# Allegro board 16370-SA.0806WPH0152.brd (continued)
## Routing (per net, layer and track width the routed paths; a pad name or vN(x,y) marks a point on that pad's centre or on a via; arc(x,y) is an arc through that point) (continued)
PCIE_SLOT0_TXP7: length 50.6
  TOP w0.178: CN1.B45 68.44,51.68 arc(68.45,51.54) 68.36,51.44 68.2,51.36 arc(68.02,51.09) 67.96,50.78 67.96,49.75 65.3,45.96 62.58,31.31 62.52,31.01 58.7,10.49 58.64,10.19 58.43,9.07 57.99,6.68 57.99,6.27 57.65,5.93 GF1.B45
PCIE_SLOT1_CPRSNT1_N: length 110.1
  TOP w0.178: v1(51.17,59.51) 51.72,58.96 55.79,58.96 56.18,58.85 56.43,58.85 58.06,57.23 58.06,56.38 58.58,55.85 70.58,55.85 71.14,55.29 71.14,51.86 72.15,50.84 72.15,49.45 66.68,41.63 64.86,31.31 64.8,31.01 60.65,7.46 GF1.B48 ; CN2.B31 52.76,74.03 47.24,74.03 46.73,73.53 41.77,73.53 40.95,72.71 CN2.B17 40.09,69.3 40.83,68.55 41.23,67.99 42.59,66.63 42.8,66.48 44.02,64.73 45.54,63.67 46.1,63.28 46.24,63.25 47.26,63.08 49.39,61.58 49.41,61.57 v1(49.44,61.57)
  BOTTOM w0.178: v1(51.17,59.51) 49.44,61.24 v1(49.44,61.57)
PCIE_SLOT1_CPRSNT2_N: length 77.6
  TOP w0.178: GF1.B81 93.65,6.95 95.65,18.31 95.65,19.47 93.08,34.06 93,34.52 89.05,56.93 87.6,58.99 83.6,64.7 79.39,67.65 77.25,68.2 74.06,68.76 CN2.B48
PCIE_SLOT1_CPRSNT3_N: length 75.5
  TOP w0.178: CN2.B81 104.09,57.12 107.23,39.29 107.53,37.64 107.61,37.18 107.65,36.93 107.94,35.29 127.69,7.09 127.7,7.08 127.7,5.9 127.65,5.84 GF1.B115
PCIE_SLOT1_RXN0: length 101
  BOTTOM w0.178: CN2.A17 39.74,75.91 arc(39.63,76) 39.5,75.99 39.34,75.91 arc(39.28,75.82) 39.25,75.7 39.25,72.36 arc(39.28,72.24) 39.34,72.14 40.02,71.47 arc(40.19,71.22) 40.25,70.92 40.25,70.17 40.33,69.69 40.69,69.18 51.54,61.58 72.53,57.88 74.22,56.7 75.04,55.52 75.65,54.66 75.69,54.61 75.71,54.52 75.9,53.42 75.9,53.21 71.06,25.75 71.01,25.45 68.73,12.51 68.36,11.99 68.36,11.77 68.06,11.34 67.88,11.3 67.58,10.87 67.61,10.69 67.3,10.26 67.13,10.23 66.82,9.79 66.85,9.62 66.55,9.18 66.37,9.15 65.28,7.58 65.28,6.28 65.65,5.91 GF1.A53
PCIE_SLOT1_RXN1: length 97.1
  BOTTOM w0.178: GF1.A57 69.65,5.93 69.31,6.27 69.31,6.88 69.54,8.18 69.57,8.33 69.8,9.62 69.84,9.87 72.59,25.45 72.64,25.75 77.42,52.87 76.99,55.29 75.31,57.69 73.15,59.2 52.29,62.88 47.79,66.03 46.7,67.59 46.7,67.59 46.25,70.14 46.25,70.89 arc(46.19,71.24) 45.99,71.53 45.44,72.08 arc(45.29,72.3) 45.24,72.56 45.24,75.55 arc(45.17,75.89) 44.98,76.18 44.82,76.26 44.82,76.26 arc(44.73,76.36) 44.74,76.5 CN2.A22
PCIE_SLOT1_RXN2: length 95
  BOTTOM w0.178: CN2.A26 48.74,76.5 arc(48.73,76.36) 48.82,76.26 48.82,76.26 48.98,76.18 arc(49.17,75.89) 49.24,75.55 49.24,72.56 arc(49.29,72.3) 49.44,72.08 49.99,71.53 arc(50.19,71.24) 50.25,70.89 50.25,70.09 50.36,69.47 50.43,69.31 50.43,69.31 51.89,65.78 54.24,64.14 73.43,60.75 73.53,60.65 76.31,58.7 78.36,55.78 80.15,45.58 73.32,6.81 73.32,6.26 73.65,5.93 GF1.A61
PCIE_SLOT1_RXN3: length 93.1
  BOTTOM w0.178: GF1.A65 77.65,5.93 77.31,6.28 77.31,6.78 77.46,7.62 77.81,9.62 78.04,10.95 78.14,11.5 78.16,11.59 78.16,11.6 82.88,38.36 79.72,56.3 77.35,59.69 76.77,60.26 74.05,62.17 56.59,65.25 56.16,65.55 55.73,65.85 54.63,67.42 54.59,67.75 54.25,70.35 54.25,70.37 54.25,70.89 arc(54.19,71.24) 53.99,71.53 53.44,72.08 arc(53.29,72.3) 53.24,72.56 53.24,75.55 arc(53.17,75.89) 52.98,76.18 52.82,76.26 52.82,76.26 arc(52.73,76.36) 52.74,76.5 CN2.A30
PCIE_SLOT1_RXN4: length 88.9
  BOTTOM w0.178: GF1.A69 81.65,5.93 81.32,6.26 81.32,6.97 85.59,31.15 81.07,56.87 78.03,61.21 74.62,63.59 63.53,65.55 60.55,67.63 60.25,69.32 60.25,70.89 arc(60.19,71.24) 59.99,71.53 59.44,72.08 arc(59.29,72.3) 59.24,72.56 59.24,75.55 arc(59.17,75.89) 58.98,76.18 58.82,76.26 58.82,76.26 arc(58.73,76.36) 58.74,76.5 CN2.A36
PCIE_SLOT1_RXN5: length 86.3
  BOTTOM w0.178: GF1.A73 85.65,5.77 85.33,6.1 85.33,9.18 88.16,25.45 82.53,57.47 79.29,62.1 75.09,65.04 71.36,65.7 70.19,65.9 69.82,65.97 67.23,66.42 65.34,67.75 64.89,68.06 64.57,68.85 64.56,68.85 64.57,68.85 64.5,69.01 64.25,70.4 64.25,70.89 arc(64.19,71.24) 63.99,71.53 63.44,72.08 arc(63.29,72.3) 63.24,72.56 63.24,75.55 arc(63.17,75.89) 62.98,76.18 62.82,76.26 arc(62.73,76.36) 62.74,76.5 CN2.A40
PCIE_SLOT1_RXN6: length 84.1
  BOTTOM w0.178: GF1.A77 89.65,5.93 89.34,6.25 89.34,6.67 91.12,16.78 91.12,17.7 90.46,21.46 90.37,21.92 89.47,27.08 88.92,30.18 85.74,47.34 84.35,56.66 84.31,56.89 84.17,57.71 80.24,63.31 75.89,66.35 70.81,67.25 69.21,68.37 68.37,69.57 68.25,70.23 68.25,70.89 arc(68.19,71.24) 67.99,71.53 67.44,72.08 arc(67.29,72.3) 67.24,72.56 67.24,75.55 arc(67.17,75.89) 66.98,76.18 66.82,76.26 arc(66.73,76.36) 66.74,76.5 CN2.A44
PCIE_SLOT1_RXN7: length 81.9
  BOTTOM w0.178: GF1.A81 93.65,5.93 93.34,6.24 93.34,7.21 93.91,10.46 91.97,21.46 91.89,21.92 85.45,58.46 83.8,60.81 81.38,64.27 76.24,67.87 74.21,68.23 72.46,69.46 72.39,69.62 72.39,69.63 72.33,69.79 72.25,70.2 72.25,70.95 arc(72.19,71.27) 72.02,71.53 71.54,72 71.4,72.15 arc(71.28,72.32) 71.24,72.54 71.24,75.55 arc(71.17,75.89) 70.98,76.18 70.82,76.26 arc(70.73,76.36) 70.74,76.5 CN2.A48
PCIE_SLOT1_RXN8: length 80.8
  BOTTOM w0.178: GF1.A86 98.65,5.93 98.26,6.32 98.26,8.03 98.25,8.06 97.99,9.58 98.09,9.73 97.99,10.25 97.85,10.35 97.76,10.88 97.86,11.02 97.77,11.55 97.62,11.65 97.53,12.18 97.63,12.32 97.54,12.85 97.39,12.95 95.89,21.46 95.81,21.92 90.14,54.06 90.04,54.63 89.9,54.84 82.68,65.15 76.89,69.2 76.53,69.64 76.53,69.65 76.42,69.78 76.24,70.2 76.24,70.99 arc(76.19,71.27) 76.03,71.51 75.47,72.06 arc(75.31,72.3) 75.25,72.59 75.25,75.7 arc(75.28,75.82) 75.34,75.91 75.5,75.99 arc(75.63,76) 75.74,75.91 CN2.A53
PCIE_SLOT1_RXN9: length 79.9
  BOTTOM w0.178: GF1.A90 102.65,5.93 102.27,6.31 102.27,7.01 102.24,7.21 102.1,8.01 102.2,8.16 102.11,8.68 101.96,8.78 101.87,9.31 101.46,11.62 99.73,21.46 99.64,21.92 94.55,50.82 84.92,64.57 84.48,65.2 83.24,66.96 83.27,67.14 82.96,67.59 82.79,67.62 82.47,68.06 82.51,68.24 82.19,68.68 82.02,68.71 81.71,69.16 80.38,70.09 80.23,70.3 80.23,70.8 arc(80.15,71.18) 79.94,71.51 79.46,71.98 arc(79.31,72.21) 79.25,72.49 79.25,75.7 arc(79.28,75.82) 79.34,75.91 79.5,75.99 arc(79.63,76) 79.74,75.91 CN2.A57
PCIE_SLOT1_RXN10: length 79.7
  BOTTOM w0.178: CN2.A61 83.74,75.91 arc(83.63,76) 83.5,75.99 83.34,75.91 arc(83.28,75.82) 83.25,75.7 83.25,72.46 arc(83.3,72.25) 83.42,72.07 83.95,71.53 arc(84.17,71.21) 84.24,70.83 84.24,70.4 84.78,67.37 85.08,66.93 85.26,66.9 85.56,66.47 85.53,66.29 85.84,65.86 86.01,65.83 86.32,65.39 86.29,65.22 86.59,64.78 86.77,64.75 87.07,64.31 87.04,64.14 99.23,46.73 106.29,6.67 106.29,6.26 106.65,5.91 GF1.A94
PCIE_SLOT1_RXN11: length 79.8
  BOTTOM w0.178: GF1.A98 110.65,5.87 110.27,6.25 110.27,7.5 109.94,9.37 109.89,9.67 109.59,11.39 109.59,11.4 109.57,11.49 109.48,12.02 109.36,12.69 109.36,12.69 109.34,12.79 104.13,42.34 89.46,63.3 89.17,64.93 89.27,65.07 89.18,65.61 89.03,65.71 88.94,66.25 89.04,66.4 88.94,66.93 88.8,67.03 88.7,67.57 88.81,67.72 88.71,68.25 88.57,68.35 88.26,70.11 88.26,70.91 arc(88.19,71.24) 88,71.52 87.41,72.11 arc(87.29,72.28) 87.25,72.49 87.25,75.7 arc(87.28,75.82) 87.34,75.91 87.5,75.99 arc(87.63,76) 87.74,75.91 CN2.A65
PCIE_SLOT1_RXN12: length 79.8
  BOTTOM w0.178: GF1.A102 114.65,6.01 114.29,6.37 114.29,7.57 114.18,8.17 113.48,12.16 111.84,21.46 111.76,21.92 108.9,38.1 108.4,38.82 94.11,59.23 93.69,61.58 93.79,61.72 93.7,62.25 93.56,62.35 93.46,62.87 93.57,63.02 93.47,63.54 93.33,63.64 93.24,64.17 93.34,64.31 93.24,64.84 93.1,64.94 92.88,66.2 92.24,69.79 92.24,70.81 arc(92.16,71.23) 91.92,71.59 91.51,72 arc(91.3,72.31) 91.23,72.68 91.23,75.51 arc(91.27,75.73) 91.39,75.93 91.5,75.99 91.5,75.99 arc(91.63,76) 91.74,75.91 CN2.A69
PCIE_SLOT1_RXN13: length 79.8
  BOTTOM w0.178: GF1.A106 118.65,6.07 118.29,6.43 118.29,8.15 115.94,21.46 115.86,21.92 113.8,33.63 98.93,54.87 97.81,61.2 97.91,61.35 97.82,61.89 97.67,61.99 97.58,62.52 97.68,62.67 97.58,63.21 97.44,63.31 97.34,63.84 97.45,63.99 97.35,64.53 97.21,64.63 96.23,70.15 96.23,70.91 arc(96.16,71.26) 95.96,71.56 95.42,72.1 arc(95.29,72.3) 95.24,72.53 95.24,75.67 arc(95.27,75.8) 95.34,75.91 95.5,75.99 arc(95.63,76) 95.74,75.91 CN2.A73
PCIE_SLOT1_RXN14: length 79.8
  BOTTOM w0.178: GF1.A110 122.65,6.06 122.28,6.43 122.28,7.29 120.28,18.61 119.78,21.46 119.7,21.92 118.32,29.72 103.68,50.64 103.11,53.86 103.21,54 103.12,54.54 102.97,54.64 102.88,55.18 102.98,55.32 102.88,55.86 102.74,55.96 102.64,56.5 102.75,56.65 102.65,57.18 102.51,57.28 100.22,70.25 100.22,71 arc(100.16,71.32) 99.98,71.58 99.34,72.22 99.23,72.49 99.23,75.64 arc(99.26,75.79) 99.34,75.91 99.5,75.99 arc(99.63,76) 99.74,75.91 CN2.A77
PCIE_SLOT1_RXN15: length 79.8
  BOTTOM w0.178: CN2.A81 103.74,75.91 arc(103.63,76) 103.5,75.99 103.5,75.99 103.34,75.91 arc(103.25,75.77) 103.22,75.61 103.22,72.43 arc(103.24,72.32) 103.31,72.22 103.93,71.6 arc(104.19,71.2) 104.28,70.73 104.28,69.97 106.95,54.87 107.09,54.77 107.18,54.24 107.08,54.09 107.18,53.55 107.32,53.45 107.42,52.91 107.32,52.77 107.41,52.23 107.56,52.13 107.65,51.59 107.55,51.45 108.44,46.37 123.02,25.55 123.66,21.92 123.74,21.46 125.33,12.45 125.97,8.85 126.09,8.17 126.17,7.68 126.2,7.53 126.22,7.43 126.29,7.02 126.29,6.36 126.65,6 GF1.A114
PCIE_SLOT1_RXP0: length 101
  BOTTOM w0.178: CN2.A16 39.44,76.5 arc(39.45,76.37) 39.36,76.26 39.17,76.16 arc(39.15,76.15) 39.12,76.13 arc(39,75.93) 38.95,75.71 38.95,72.36 arc(39,72.12) 39.13,71.93 39.8,71.25 arc(39.9,71.1) 39.94,70.92 39.94,70.15 40.04,69.57 40.47,68.96 51.42,61.29 72.41,57.59 74,56.48 74.94,55.14 75.41,54.47 75.6,53.39 75.6,53.24 70.75,25.75 70.7,25.45 68.44,12.63 68.11,12.16 68.08,12.12 66.5,9.86 66.12,9.32 64.97,7.68 64.97,6.26 64.65,5.93 GF1.A52
PCIE_SLOT1_RXP1: length 97.1
  BOTTOM w0.178: GF1.A56 68.65,5.89 69.01,6.25 69.01,6.91 69.24,8.23 69.28,8.48 69.49,9.67 69.54,9.92 69.67,10.68 69.57,10.82 69.66,11.35 69.81,11.45 69.9,11.97 69.8,12.12 69.89,12.64 70.04,12.74 70.13,13.27 70.03,13.41 70.12,13.94 70.26,14.04 72.28,25.45 72.33,25.75 77.11,52.87 76.7,55.17 75.49,56.9 75.09,57.47 73.03,58.92 52.17,62.59 47.57,65.81 46.42,67.47 46.4,67.54 45.95,70.11 45.95,70.89 arc(45.9,71.12) 45.77,71.32 45.22,71.87 arc(45.01,72.19) 44.93,72.56 44.93,75.55 arc(44.9,75.75) 44.79,75.93 44.68,75.99 44.68,75.99 arc(44.55,76) 44.44,75.91 CN2.A21
PCIE_SLOT1_RXP2: length 95
  BOTTOM w0.178: CN2.A25 48.44,75.91 arc(48.55,76) 48.68,75.99 48.68,75.99 48.79,75.93 arc(48.9,75.75) 48.93,75.55 48.93,72.56 arc(49.01,72.19) 49.22,71.87 49.77,71.32 arc(49.9,71.12) 49.95,70.89 49.95,70.12 49.95,70.06 50.08,69.35 50.14,69.19 50.15,69.19 51.64,65.59 54.12,63.85 73.26,60.47 73.28,60.47 73.34,60.42 76.1,58.49 76.62,57.73 77.82,56.02 78.07,55.66 79.85,45.58 73.95,12.15 73.81,12.05 73.71,11.52 73.81,11.38 73.72,10.85 73.58,10.75 73.48,10.23 73.59,10.08 73.49,9.56 73.35,9.46 73.26,8.93 73.36,8.79 73.01,6.84 73.01,6.3 72.65,5.93 GF1.A60
PCIE_SLOT1_RXP3: length 93.1
  BOTTOM w0.178: CN2.A29 52.44,75.91 arc(52.55,76) 52.68,75.99 52.68,75.99 52.79,75.93 arc(52.9,75.75) 52.93,75.55 52.93,72.56 arc(53.01,72.19) 53.22,71.87 53.77,71.32 arc(53.9,71.12) 53.95,70.89 53.95,70.33 54.34,67.31 55.52,65.63 56.47,64.96 73.93,61.88 76.58,60.03 77.11,59.49 79.43,56.18 82.57,38.36 79.81,22.73 78.61,15.93 78.47,15.82 78.37,15.3 78.47,15.16 78.38,14.63 78.24,14.53 78.15,14 78.25,13.86 78.15,13.33 78.01,13.23 77.92,12.71 78.02,12.56 77.85,11.62 77.85,11.62 77.84,11.55 77.74,11 77.51,9.67 77.16,7.67 77,6.81 77,6.27 76.65,5.91 GF1.A64
PCIE_SLOT1_RXP4: length 88.9
  BOTTOM w0.178: CN2.A35 58.44,75.91 arc(58.55,76) 58.68,75.99 58.68,75.99 58.79,75.93 arc(58.9,75.75) 58.93,75.55 58.93,72.56 arc(59.01,72.19) 59.22,71.87 59.77,71.32 arc(59.9,71.12) 59.95,70.89 59.95,69.29 60.27,67.46 63.41,65.26 74.5,63.31 77.81,60.99 80.78,56.75 85.28,31.15 82.28,14.18 82.14,14.08 82.05,13.56 82.15,13.41 82.06,12.89 81.91,12.79 81.82,12.26 81.92,12.12 81.83,11.59 81.68,11.49 81.59,10.97 81.69,10.82 81.02,7 81.02,6.27 80.65,5.9 GF1.A68
PCIE_SLOT1_RXP5: length 86.3
  BOTTOM w0.178: CN2.A39 62.44,75.91 arc(62.55,76) 62.68,75.99 62.68,75.99 62.79,75.93 arc(62.9,75.75) 62.93,75.55 62.93,72.56 arc(63.01,72.19) 63.22,71.87 63.77,71.32 arc(63.9,71.12) 63.95,70.89 63.95,70.38 64.21,68.89 64.28,68.73 64.28,68.73 64.64,67.86 64.72,67.81 65.16,67.5 67.11,66.14 69.77,65.67 71.31,65.39 74.97,64.75 79.07,61.88 82.24,57.35 87.85,25.45 85.98,14.69 85.84,14.59 85.74,14.06 85.85,13.92 85.75,13.39 85.61,13.29 85.52,12.77 85.62,12.62 85.53,12.1 85.38,12 85.29,11.47 85.39,11.33 85.02,9.2 85.02,6.11 84.65,5.73 GF1.A72
PCIE_SLOT1_RXP6: length 84.1
  BOTTOM w0.178: CN2.A43 66.44,75.91 arc(66.55,76) 66.68,75.99 66.68,75.99 66.79,75.93 arc(66.9,75.75) 66.93,75.55 66.93,72.56 arc(67.01,72.19) 67.22,71.87 67.77,71.32 arc(67.9,71.12) 67.95,70.89 67.95,70.2 68.08,69.45 68.99,68.15 70.69,66.96 70.76,66.95 73.3,66.5 75.77,66.06 80.03,63.09 83.88,57.59 84.03,56.74 84.03,56.74 84.05,56.61 85.44,47.29 88.62,30.12 89.72,23.91 90.07,21.92 90.15,21.46 90.81,17.67 90.81,16.8 90.32,14.02 89.84,11.27 89.69,11.17 89.6,10.65 89.7,10.5 89.61,9.98 89.47,9.88 89.37,9.35 89.47,9.21 89.38,8.68 89.24,8.58 89.15,8.06 89.25,7.91 89.03,6.69 89.03,6.25 88.65,5.87 GF1.A76
PCIE_SLOT1_RXP7: length 81.9
  BOTTOM w0.178: GF1.A80 92.65,5.93 93.04,6.32 93.04,7.24 93.04,7.27 93.6,10.46 93.45,11.35 93.3,11.45 93.21,11.97 93.31,12.12 93.22,12.64 93.07,12.74 92.98,13.27 93.08,13.41 92.99,13.94 92.85,14.04 92.75,14.56 92.85,14.71 91.66,21.46 91.58,21.92 85.16,58.34 83.55,60.64 81.16,64.05 76.12,67.58 74.09,67.94 73.16,68.59 72.21,69.26 72.11,69.51 72.11,69.51 72.04,69.67 71.95,70.17 71.95,70.95 arc(71.91,71.15) 71.8,71.31 71.18,71.93 arc(71,72.21) 70.93,72.54 70.93,75.55 arc(70.9,75.75) 70.79,75.93 70.68,75.99 70.68,75.99 arc(70.55,76) 70.44,75.91 CN2.A47
PCIE_SLOT1_RXP8: length 80.7
  BOTTOM w0.178: GF1.A85 97.65,5.93 97.95,6.24 97.95,8.01 96.37,16.98 95.58,21.46 95.5,21.92 89.84,54 89.75,54.51 82.46,64.93 76.68,68.97 76.47,69.23 76.29,69.45 76.29,69.45 76.18,69.58 75.94,70.14 75.94,70.99 arc(75.9,71.15) 75.81,71.29 75.26,71.85 arc(75.03,72.19) 74.95,72.59 74.95,75.71 arc(75,75.93) 75.12,76.13 arc(75.15,76.15) 75.17,76.16 75.36,76.26 arc(75.45,76.37) 75.44,76.5 CN2.A52
PCIE_SLOT1_RXP9: length 80
  BOTTOM w0.178: CN2.A56 79.44,76.5 arc(79.45,76.37) 79.36,76.26 79.17,76.16 arc(79.15,76.15) 79.12,76.13 arc(79,75.93) 78.95,75.71 78.95,72.49 arc(79.03,72.1) 79.25,71.77 79.72,71.29 arc(79.87,71.07) 79.93,70.8 79.93,70.18 79.98,70.13 80.16,69.87 81.49,68.94 83.2,66.49 83.2,66.49 84.23,65.03 84.45,64.71 84.67,64.39 94.26,50.7 99.34,21.92 99.42,21.46 101.16,11.57 101.53,9.5 101.94,7.15 101.97,6.98 101.97,6.25 101.65,5.93 GF1.A89
PCIE_SLOT1_RXP10: length 79.7
  BOTTOM w0.178: CN2.A60 83.44,76.5 arc(83.45,76.37) 83.36,76.26 83.17,76.16 arc(83.15,76.15) 83.12,76.13 arc(83,75.93) 82.95,75.71 82.95,72.46 arc(83.02,72.13) 83.2,71.85 83.74,71.32 arc(83.89,71.09) 83.94,70.83 83.94,70.83 83.94,70.38 84.49,67.25 98.94,46.61 105.99,6.64 105.99,6.27 105.65,5.93 GF1.A93
PCIE_SLOT1_RXP11: length 79.8
  BOTTOM w0.178: CN2.A64 87.44,76.5 arc(87.45,76.37) 87.36,76.26 87.17,76.16 arc(87.15,76.15) 87.12,76.13 arc(87,75.93) 86.95,75.71 86.95,72.49 arc(87.01,72.17) 87.19,71.9 87.79,71.3 arc(87.91,71.12) 87.95,70.91 87.95,70.09 89.17,63.18 103.84,42.23 109.05,12.67 109.05,12.66 109.18,11.96 109.27,11.44 109.28,11.37 109.28,11.37 109.59,9.62 109.64,9.31 109.97,7.47 109.97,6.25 109.65,5.93 GF1.A97
PCIE_SLOT1_RXP12: length 79.8
  BOTTOM w0.178: GF1.A101 113.65,6.01 113.98,6.34 113.98,7.54 113.88,8.12 113.18,12.11 111.53,21.46 111.45,21.92 108.62,37.98 108.09,38.73 101.26,48.49 94.84,57.66 93.82,59.11 92.58,66.15 91.94,69.77 91.94,70.81 arc(91.88,71.11) 91.7,71.38 91.29,71.79 arc(91.02,72.19) 90.92,72.68 90.92,75.51 arc(91,75.87) 91.2,76.18 91.36,76.26 91.36,76.26 arc(91.45,76.36) 91.44,76.5 CN2.A68
PCIE_SLOT1_RXP13: length 79.8
  BOTTOM w0.178: CN2.A72 95.44,76.5 arc(95.45,76.37) 95.36,76.26 95.17,76.16 arc(95,75.94) 94.94,75.67 94.94,72.53 arc(95.01,72.18) 95.2,71.89 95.75,71.34 arc(95.88,71.15) 95.93,70.91 95.93,70.12 98.64,54.75 113.51,33.51 115.55,21.92 115.63,21.46 115.75,20.82 117.98,8.12 117.98,6.46 117.65,6.12 GF1.A105
PCIE_SLOT1_RXP14: length 79.8
  BOTTOM w0.178: CN2.A76 99.44,76.5 arc(99.45,76.37) 99.36,76.26 99.17,76.16 arc(98.99,75.93) 98.92,75.64 98.92,72.43 99.08,72.05 99.76,71.37 arc(99.88,71.2) 99.92,71 99.92,70.22 103.39,50.52 118.04,29.6 119.39,21.92 119.47,21.46 120,18.47 120,18.46 121.57,9.57 121.98,7.26 121.98,6.41 121.65,6.08 GF1.A109
PCIE_SLOT1_RXP15: length 79.8
  BOTTOM w0.178: GF1.A113 125.65,6.02 125.99,6.35 125.99,6.99 125.92,7.37 125.9,7.48 125.87,7.63 125.67,8.8 124.91,13.08 123.43,21.46 123.35,21.92 122.73,25.43 108.16,46.25 103.98,69.94 103.98,70.73 arc(103.91,71.08) 103.71,71.38 103.09,72 arc(102.96,72.2) 102.91,72.43 102.91,75.61 arc(102.98,75.92) 103.17,76.16 103.36,76.26 103.36,76.26 arc(103.45,76.37) 103.44,76.5 CN2.A80
PCIE_SLOT1_TXN0: length 100.9
  TOP w0.178: GF1.B51 63.65,5.96 63.33,6.27 63.33,7.04 63.43,7.6 63.68,9 64.31,12.61 67.56,31.01 67.61,31.31 69.42,41.55 72.47,45.91 75.73,50.57 75.93,50.85 76.47,53.91 76.35,54.61 75.61,55.66 73.93,56.83 72.24,58.02 71.4,58.17 70.51,58.01 67.28,58.58 64.6,58.11 58.97,59.1 57.12,60.4 53.41,61.05 49.7,60.4 49.53,60.4 49.52,60.4 49.34,60.43 49.07,60.48 49.06,60.48 48.92,60.58 47.92,61.28 46.83,62.04 46.71,62.06 46.16,62.16 45.58,62.26 45.42,62.42 43.24,63.95 42.01,65.7 41,66.4 40.05,67.77 38.7,68.71 38.46,69.06 38.24,70.26 38.24,71.04 arc(38.17,71.39) 37.98,71.68 37.82,71.76 37.82,71.76 arc(37.73,71.86) 37.74,72 CN2.B15
PCIE_SLOT1_TXN1: length 96.7
  TOP w0.178: CN2.B20 42.74,71.41 arc(42.63,71.5) 42.5,71.49 42.39,71.43 arc(42.32,71.33) 42.27,71.22 arc(42.24,71.12) 42.23,71.02 42.23,71.02 42.23,70.58 42.38,69.74 42.86,69.05 46.2,66.71 46.38,66.74 46.81,66.44 46.85,66.26 47.28,65.96 47.46,65.99 47.89,65.68 47.92,65.51 48.36,65.2 48.53,65.23 48.97,64.93 49,64.75 51.88,62.74 54.69,62.24 54.73,62.23 57.66,61.72 59.52,60.42 64.59,59.53 67.37,60.02 69.97,59.56 70.87,59.71 73.76,59.21 75.89,57.72 76.79,56.43 77.7,55.12 77.79,54.63 77.94,53.79 77.32,50.29 77.08,49.94 75.56,47.77 74.06,45.64 71.54,31.31 71.48,31.01 68.24,12.61 67.28,7.14 67.28,6.37 67.65,5.99 GF1.B55
PCIE_SLOT1_TXN2: length 93.7
  TOP w0.178: CN2.B24 46.74,71.41 arc(46.63,71.5) 46.5,71.49 46.35,71.34 46.23,71.07 46.23,70.35 47.18,68.89 47.18,68.89 47.26,68.81 49.8,66.59 50.52,66.09 50.69,66.12 51.13,65.81 51.16,65.64 51.6,65.33 51.77,65.36 52.21,65.06 52.24,64.88 53.66,63.89 54.18,63.8 54.33,63.9 54.85,63.81 54.95,63.66 56.25,63.43 58.25,63.08 60.13,61.76 64.67,60.96 67.41,61.44 69.98,60.99 70.88,61.15 74.38,60.53 76.97,58.72 79.05,55.77 79.44,53.52 71.6,9.03 71.7,8.89 71.64,8.58 71.41,7.98 71.34,7.57 71.34,6.22 71.65,5.91 GF1.B59
PCIE_SLOT1_TXN3: length 92.2
  TOP w0.178: GF1.B63 75.65,5.97 75.28,6.34 75.28,7.16 77.15,17.76 79.48,31.01 79.54,31.31 82.17,46.23 80.38,56.37 77.74,60.13 75.37,61.8 70.71,62.62 69.79,62.45 67.44,62.87 64.79,62.4 60.66,63.13 60.38,63.33 60.09,63.53 58.83,64.41 57.66,64.62 57.56,64.76 57.03,64.86 56.89,64.76 56.36,64.85 54.75,65.58 54.69,65.75 54.21,65.97 54.04,65.91 53.56,66.13 53.5,66.3 53.01,66.52 52.85,66.46 52.2,66.75 51.31,67.67 50.74,68.26 50.23,69.99 50.23,71.02 50.23,71.02 arc(50.27,71.24) 50.39,71.43 50.5,71.49 arc(50.63,71.5) 50.74,71.41 CN2.B28
PCIE_SLOT1_TXN4: length 88.4
  TOP w0.178: GF1.B67 79.65,5.91 79.28,6.27 79.28,6.94 79.45,7.86 83.53,31.01 83.58,31.31 84.06,34 84.94,38.99 81.76,57.03 81.65,57.13 78.88,61.09 76.01,63.11 70.7,64.04 69.81,63.88 67.43,64.3 64.83,63.84 61.34,64.46 60.19,65.26 60.16,65.43 59.72,65.74 59.55,65.71 59.11,66.02 59.08,66.19 58.65,66.5 58.47,66.46 58.04,66.77 57.2,67.97 57.23,68.14 56.92,68.58 56.75,68.61 56.44,69.05 56.23,70.23 56.23,71.23 56.3,71.37 56.37,71.43 56.5,71.49 56.5,71.49 arc(56.63,71.5) 56.74,71.41 CN2.B34
PCIE_SLOT1_TXN5: length 86.9
  TOP w0.178: GF1.B71 83.65,6.02 83.28,6.39 83.28,6.81 83.39,7.41 83.39,7.41 83.41,7.54 83.44,7.7 83.74,9.44 83.75,9.44 83.77,9.57 86.07,22.61 86.4,24.49 87.67,31.68 83.08,57.68 80.03,62.04 76.6,64.44 70.65,65.49 69.91,65.35 67.56,65.77 66.18,65.53 66.03,65.63 65.51,65.54 65.41,65.39 64.88,65.3 63.16,65.6 63.06,65.75 62.54,65.84 62.39,65.74 61.87,65.83 61.47,66.11 60.78,67.09 60.46,68.9 60.56,69.05 60.47,69.57 60.33,69.67 60.23,70.2 60.23,71.02 60.23,71.02 arc(60.27,71.24) 60.39,71.43 60.5,71.49 60.5,71.49 arc(60.63,71.5) 60.74,71.41 CN2.B38
PCIE_SLOT1_TXN6: length 83.6
  TOP w0.178: CN2.B42 64.74,71.41 arc(64.63,71.5) 64.5,71.49 64.5,71.49 64.39,71.43 arc(64.27,71.24) 64.23,71.02 64.23,71.02 64.23,70.16 64.45,68.91 64.66,68.63 66.37,67.42 66.37,67.42 69.83,66.81 70.64,66.96 72.15,66.69 72.3,66.79 72.82,66.7 72.92,66.56 73.45,66.46 73.59,66.56 74.12,66.47 74.22,66.33 74.74,66.23 74.89,66.34 75.41,66.24 75.51,66.1 77.17,65.81 81.18,63 84.4,58.4 88.61,34.52 88.69,34.06 90.36,24.57 90.27,24.07 89.61,20.3 89.61,20.3 88.81,15.77 88.81,15.77 87.27,7.02 87.27,6.44 87.65,6.06 GF1.B75
PCIE_SLOT1_TXN7: length 81.1
  TOP w0.178: CN2.B46 68.74,71.41 arc(68.63,71.5) 68.5,71.49 68.5,71.49 68.39,71.43 arc(68.27,71.24) 68.23,71.02 68.23,71.02 68.23,70.2 68.6,69.34 69.12,68.9 69.24,68.84 69.77,68.74 69.91,68.84 70.44,68.75 70.54,68.6 71.06,68.51 71.21,68.61 71.73,68.51 71.83,68.36 72.36,68.27 72.5,68.37 73.03,68.27 73.13,68.13 77.51,67.33 82.37,63.92 85.81,59.01 90.13,34.52 90.21,34.06 93.05,17.98 92.45,14.58 91.67,10.15 91.29,8.03 91.29,6.38 91.65,6.02 GF1.B79
PCIE_SLOT1_TXN8: length 79.5
  TOP w0.178: GF1.B84 96.65,5.98 96.33,6.29 96.33,8.58 97.74,16.56 94.65,34.06 94.57,34.52 90.51,57.54 84.98,65.45 84.83,65.59 84.83,65.6 84.71,65.72 80.58,68.61 77.37,69.17 76.55,69.85 76.24,70.3 76.24,71.01 arc(75.98,71.64) 75.35,71.9 74.91,71.9 arc(74.71,71.86) 74.54,71.75 74.47,71.68 arc(74.24,71.58) 74,71.66 arc(73.99,71.67) 73.98,71.68 73.82,71.76 arc(73.73,71.86) 73.74,72 CN2.B51
PCIE_SLOT1_TXN9: length 77.7
  TOP w0.178: CN2.B55 77.74,72 arc(77.73,71.86) 77.82,71.76 77.98,71.68 arc(77.99,71.67) 78,71.66 arc(78.21,71.59) 78.41,71.68 arc(78.6,71.81) 78.82,71.85 79.39,71.85 arc(79.98,71.6) 80.23,71.01 80.23,70.53 80.34,69.91 80.48,69.72 81.77,68.81 83.12,68.57 85.89,66.64 92.66,56.96 96.62,34.52 96.7,34.06 99.59,17.63 100.48,12.57 100.94,10 100.32,6.52 100.32,6.09 100.65,5.76 GF1.B88
PCIE_SLOT1_TXN10: length 76.1
  TOP w0.178: GF1.B92 104.65,5.88 104.33,6.2 104.33,8.78 102.06,12.02 93.83,58.68 88.19,66.74 84.74,69.15 83.07,69.45 82.53,69.83 82.32,70.12 82.24,70.58 82.24,71.05 81.98,71.68 81.82,71.76 arc(81.73,71.86) 81.74,72 CN2.B59
PCIE_SLOT1_TXN11: length 75.1
  TOP w0.178: GF1.B96 108.65,5.97 108.32,6.3 108.32,7.65 106.46,10.3 102.95,15.32 99.65,34.06 99.56,34.52 95.16,59.51 89.15,68.08 86.53,69.92 86.3,70.25 86.22,70.66 86.22,71.22 arc(86.17,71.46) 86.01,71.66 85.82,71.76 arc(85.73,71.87) 85.74,72 CN2.B63
PCIE_SLOT1_TXN12: length 74.7
  TOP w0.178: CN2.B67 89.74,72 arc(89.73,71.86) 89.82,71.76 89.98,71.68 arc(90.18,71.38) 90.25,71.02 90.25,70.11 90.31,69.78 96.32,61.21 101.02,34.52 101.1,34.06 103.62,19.78 106.29,15.96 109.65,11.16 110.82,9.5 111.54,8.47 112.32,7.36 112.32,6.32 112.65,5.99 GF1.B100
PCIE_SLOT1_TXN13: length 74.7
  TOP w0.178: CN2.B71 93.74,72 arc(93.73,71.86) 93.82,71.76 93.98,71.68 arc(94,71.66) 94.02,71.63 arc(94.19,71.35) 94.25,71.02 94.25,70.03 95.22,68.66 96.02,67.51 96.51,66.81 96.86,66.31 96.86,66.3 102.46,34.52 102.54,34.06 103.46,28.86 104.28,24.19 111.54,13.82 111.56,13.8 111.99,13.18 115.38,8.35 116.32,6.99 116.32,6.37 116.65,6.04 GF1.B104
PCIE_SLOT1_TXN14: length 74.9
  TOP w0.178: GF1.B108 120.65,6.06 120.31,6.39 120.31,7.38 119.96,7.89 119.11,9.09 119.11,9.1 118.66,9.74 116.94,12.19 104.81,29.52 98.25,66.7 98.25,70.13 98.25,70.15 arc(98.25,70.16) 98.25,70.16 98.25,71.02 arc(98.18,71.38) 97.98,71.68 97.82,71.76 arc(97.73,71.86) 97.74,72 CN2.B75
PCIE_SLOT1_TXN15: length 75.9
  TOP w0.178: CN2.B79 101.74,72 arc(101.73,71.87) 101.82,71.76 102.01,71.66 arc(102.19,71.43) 102.25,71.15 102.25,70.57 101.16,64.37 100.7,61.75 105.69,33.44 124.31,6.85 124.31,6.23 124.65,5.89 GF1.B112
PCIE_SLOT1_TXP0: length 100.9
  TOP w0.178: CN2.B14 37.44,71.41 arc(37.55,71.5) 37.68,71.49 37.68,71.49 37.79,71.43 arc(37.9,71.25) 37.94,71.04 37.94,71.04 37.94,70.23 38.17,68.94 38.48,68.49 39.83,67.55 40.78,66.19 41.8,65.48 43.02,63.73 45.22,62.19 45.43,61.98 46.66,61.76 46.66,61.76 46.71,61.75 47.75,61.03 48.75,60.33 48.96,60.18 49.02,60.18 49.03,60.18 49.04,60.18 49.29,60.13 49.47,60.1 49.51,60.09 49.73,60.09 53.41,60.74 57,60.11 58.85,58.81 64.6,57.8 67.28,58.27 70.51,57.7 71.4,57.86 72.12,57.73 75.39,55.44 76.06,54.49 76.16,53.91 75.64,50.97 75.48,50.74 69.13,41.67 67.3,31.31 67.25,31.01 64.01,12.66 63.92,12.14 63.78,12.03 63.68,11.51 63.79,11.37 63.69,10.84 63.55,10.74 63.46,10.21 63.56,10.07 63.46,9.54 63.32,9.44 63.23,8.92 63.33,8.77 63.13,7.65 63.03,7.06 63.03,6.31 62.65,5.93 GF1.B50
PCIE_SLOT1_TXP1: length 96.7
  TOP w0.178: GF1.B54 66.65,6.05 66.97,6.37 66.97,7.17 67.94,12.67 71.17,31.01 71.23,31.31 73.77,45.76 77.03,50.41 77.63,53.79 77.49,54.57 77.41,55 75.67,57.5 73.64,58.92 70.87,59.41 69.97,59.25 67.37,59.71 64.59,59.22 59.4,60.13 57.54,61.43 54.68,61.93 54.63,61.94 53.18,62.2 51.76,62.45 42.64,68.83 42.09,69.62 41.93,70.53 41.93,70.53 41.93,71.27 41.98,71.32 arc(42.07,71.51) 42.2,71.68 42.36,71.76 arc(42.45,71.86) 42.44,72 CN2.B19
PCIE_SLOT1_TXP2: length 93.7
  TOP w0.178: CN2.B23 46.44,72 arc(46.46,71.89) 46.41,71.79 46.37,71.79 46.09,71.51 45.94,71.15 45.93,71.14 45.93,70.26 46.96,68.67 47.05,68.59 49.61,66.35 53.54,63.6 56.45,63.09 58.13,62.79 60.02,61.47 64.67,60.65 67.41,61.14 69.98,60.68 70.88,60.84 74.26,60.25 76.75,58.5 78.76,55.65 79.13,53.52 73.25,20.17 71.04,7.6 71.04,6.22 70.65,5.83 GF1.B58
PCIE_SLOT1_TXP3: length 92.2
  TOP w0.178: GF1.B62 74.65,6.02 74.97,6.34 74.97,7.18 76.57,16.23 79.17,31.01 79.23,31.31 81.86,46.23 80.09,56.25 77.52,59.92 75.25,61.51 70.71,62.31 69.79,62.14 67.44,62.56 64.79,62.09 60.54,62.84 60.21,63.08 58.71,64.12 56.27,64.55 52.03,66.5 51.09,67.46 50.81,67.76 50.47,68.11 49.93,69.95 49.93,71.02 arc(50,71.38) 50.2,71.68 50.36,71.76 arc(50.45,71.86) 50.44,72 CN2.B27
PCIE_SLOT1_TXP4: length 88.4
  TOP w0.178: GF1.B66 78.65,5.93 78.98,6.26 78.98,6.96 81.42,20.8 83.22,31.01 83.27,31.31 83.76,34.06 84.63,38.99 81.47,56.89 81.42,56.94 78.66,60.88 75.89,62.82 70.7,63.73 69.81,63.57 67.43,63.99 64.83,63.54 61.22,64.17 57.82,66.55 56.15,68.93 55.93,70.2 55.93,71.3 56.09,71.62 56.36,71.76 56.36,71.76 arc(56.45,71.86) 56.44,72 CN2.B33
PCIE_SLOT1_TXP5: length 87
  TOP w0.178: CN2.B37 60.44,72 arc(60.45,71.86) 60.36,71.76 60.2,71.68 arc(60,71.38) 59.93,71.02 59.93,70.17 60.49,66.98 61.25,65.89 61.75,65.54 64.88,64.99 67.56,65.46 69.91,65.05 70.65,65.18 76.48,64.15 79.81,61.82 82.79,57.56 87.36,31.68 86.12,24.64 86.12,24.64 85.77,22.66 83.47,9.62 83.44,9.5 83.14,7.75 83.11,7.59 83.08,7.44 82.98,6.83 82.98,6.35 82.65,6.02 GF1.B70
PCIE_SLOT1_TXP6: length 83.6
  TOP w0.178: GF1.B74 86.65,6.08 86.96,6.39 86.96,7.04 88.51,15.82 88.53,15.95 88.53,15.95 89.28,20.2 89.97,24.12 90.05,24.57 88.38,34.06 88.3,34.52 84.11,58.28 80.96,62.78 77.05,65.52 70.64,66.65 69.83,66.5 66.25,67.13 64.44,68.41 64.16,68.79 63.93,70.14 63.93,71.02 arc(64,71.38) 64.2,71.68 64.36,71.76 arc(64.45,71.86) 64.44,72 CN2.B41
PCIE_SLOT1_TXP7: length 81.1
  TOP w0.178: GF1.B78 90.65,6.04 90.99,6.38 90.99,8.05 91.37,10.2 91.84,12.87 92.15,14.64 92.74,17.98 89.9,34.06 89.82,34.52 85.52,58.89 82.16,63.7 77.39,67.04 69.13,68.55 69.13,68.55 68.97,68.63 68.35,69.15 67.93,70.14 67.93,71.02 arc(68,71.38) 68.2,71.68 68.36,71.76 arc(68.45,71.86) 68.44,72 CN2.B45
PCIE_SLOT1_TXP8: length 79.5
  TOP w0.178: GF1.B83 95.65,5.91 96.03,6.29 96.03,8.63 96.03,8.63 96.23,9.76 96.13,9.9 96.22,10.43 96.37,10.53 96.46,11.05 96.36,11.2 96.45,11.72 96.6,11.82 96.69,12.35 96.59,12.49 96.68,13.02 96.82,13.12 97.43,16.56 94.34,34.06 94.26,34.52 90.23,57.42 84.74,65.25 84.62,65.38 84.61,65.38 84.49,65.5 80.46,68.32 77.24,68.89 76.32,69.64 75.94,70.21 75.94,71.01 arc(75.77,71.43) 75.35,71.6 74.91,71.6 arc(74.83,71.58) 74.76,71.53 74.69,71.47 arc(74.25,71.27) 73.8,71.43 73.68,71.49 73.68,71.49 arc(73.55,71.5) 73.44,71.41 CN2.B50
PCIE_SLOT1_TXP9: length 77.7
  TOP w0.178: CN2.B54 77.44,71.41 arc(77.55,71.5) 77.68,71.49 77.68,71.49 77.8,71.43 arc(78.22,71.29) 78.63,71.47 arc(78.71,71.52) 78.82,71.55 79.39,71.55 arc(79.77,71.39) 79.93,71.01 79.93,70.5 80.05,69.79 80.26,69.5 81.65,68.52 83,68.28 85.67,66.42 92.37,56.84 96.31,34.52 96.39,34.06 99.45,16.65 99.55,16.12 99.45,15.98 99.54,15.46 99.68,15.35 99.78,14.83 99.67,14.69 99.77,14.16 99.91,14.06 100,13.53 99.9,13.39 100,12.86 100.14,12.76 100.18,12.51 100.4,11.28 100.63,10 100.02,6.55 100.02,6.12 99.65,5.76 GF1.B87
PCIE_SLOT1_TXP10: length 76.1
  TOP w0.178: CN2.B58 81.44,71.41 arc(81.55,71.5) 81.68,71.49 81.74,71.46 81.93,70.99 81.93,70.53 81.94,70.53 82.03,70 82.31,69.61 82.95,69.16 84.62,68.86 87.97,66.52 89.39,64.49 89.36,64.31 89.67,63.87 89.85,63.84 90.16,63.39 90.13,63.22 90.44,62.77 90.62,62.74 90.93,62.29 90.9,62.12 91.21,61.67 91.39,61.64 93.54,58.56 101.77,11.9 104.02,8.68 104.02,6.21 103.65,5.84 GF1.B91
PCIE_SLOT1_TXP11: length 75.1
  TOP w0.178: CN2.B62 85.44,71.41 arc(85.55,71.5) 85.68,71.49 85.84,71.41 arc(85.9,71.32) 85.92,71.22 85.92,70.63 86.01,70.13 86.31,69.7 88.94,67.86 89.72,66.75 89.69,66.58 89.99,66.14 90.16,66.11 90.47,65.67 90.44,65.5 90.75,65.06 90.92,65.03 91.23,64.59 91.19,64.42 91.5,63.98 91.67,63.95 94.87,59.39 99.25,34.52 99.34,34.06 102.66,15.2 103.5,14.01 106.21,10.13 108.01,7.56 108.01,6.34 107.65,5.98 GF1.B95
PCIE_SLOT1_TXP12: length 74.6
  TOP w0.178: CN2.B66 89.44,71.41 arc(89.55,71.5) 89.68,71.49 89.68,71.49 89.79,71.43 arc(89.91,71.24) 89.95,71.02 89.95,71.02 89.95,70.09 90.02,69.66 91.7,67.27 91.67,67.09 91.98,66.66 92.15,66.63 92.45,66.19 92.42,66.02 92.73,65.58 92.9,65.55 93.21,65.11 93.18,64.94 93.48,64.5 93.66,64.47 96.03,61.09 100.71,34.52 100.79,34.06 103.33,19.66 106.04,15.79 109.4,10.99 110.48,9.44 112.01,7.26 112.01,6.3 111.65,5.94 GF1.B99
PCIE_SLOT1_TXP13: length 74.6
  TOP w0.178: GF1.B103 115.65,6 116.02,6.37 116.02,6.9 114.23,9.44 111.69,13.08 111.31,13.63 111.31,13.63 103.99,24.07 103.16,28.81 102.23,34.06 102.15,34.52 97.25,62.31 97.11,62.41 97.01,62.94 97.11,63.08 97.02,63.61 96.88,63.71 96.79,64.23 96.89,64.38 96.79,64.9 96.65,65 96.56,65.53 96.66,65.67 96.57,66.2 96.26,66.64 95.77,67.33 94.97,68.48 93.95,69.94 93.95,71.02 93.95,71.02 arc(93.91,71.24) 93.79,71.43 93.74,71.46 93.68,71.49 arc(93.55,71.5) 93.44,71.41 CN2.B70
PCIE_SLOT1_TXP14: length 74.8
  TOP w0.178: GF1.B107 119.65,6.01 120.01,6.37 120.01,7.28 119.71,7.71 118.69,9.17 118.51,9.2 118.2,9.65 118.23,9.82 117.92,10.27 117.74,10.3 117.43,10.75 117.46,10.92 117.15,11.37 116.98,11.4 116.66,11.85 116.69,12.02 104.52,29.4 97.95,66.68 97.95,70.11 arc(97.95,70.14) 97.95,70.16 97.95,71.02 97.95,71.02 arc(97.91,71.24) 97.79,71.43 97.68,71.49 97.68,71.49 arc(97.55,71.5) 97.44,71.41 CN2.B74
PCIE_SLOT1_TXP15: length 75.8
  TOP w0.178: CN2.B78 101.44,71.41 arc(101.55,71.5) 101.68,71.49 101.84,71.41 arc(101.92,71.29) 101.95,71.15 101.95,70.6 101.43,67.66 101.29,67.56 101.19,67.04 101.29,66.89 101.2,66.37 101.06,66.27 100.97,65.74 101.07,65.6 100.97,65.07 100.83,64.97 100.74,64.45 100.84,64.3 100.39,61.75 105.4,33.32 124.01,6.75 124.01,6.23 123.65,5.87 GF1.B111
PCIE_SMCLK: length 52.8
  TOP w0.178: U10.1 33.82,41.29 33.55,41.01 33.55,40.2 34.18,39.57 34.93,39.57 v1(35.12,39.76) ; v1(17.19,24.91) 16.5,24.22 16.5,7.99 16.27,7.77 16.27,6.38 15.65,5.75 GF1.B5
  BOTTOM w0.178: v1(17.19,24.91) 17.19,24.91 18.46,24.91 20.62,27.07 27.2,27.07 34.19,34.06 v2(34.19,38) 34.19,38.92 35.02,39.76 v1(35.12,39.76)
PCIE_SMCLK0: length 4.6
  TOP w0.178: RE1.2 32.27,46.13 R14.2 32.48,44.85 32.48,43.61 32.11,43.24 U10.5
PCIE_SMCLK1: length 5.2
  TOP w0.178: v2(27.18,39.09) 27.19,39.09 27.54,39.44 RE10.2 27.98,40.38 28.09,40.5 28.09,40.94 28.33,41.18 R16.2 28.88,41.29 U10.8
PCIE_SMDAT: length 52.7
  TOP w0.178: v1(35.06,38.84) 34.77,39.14 34,39.14 33.11,40.02 33.11,41.19 33.86,41.94 U10.2 ; GF1.B6 16.65,6.14 16.7,6.2 16.7,7.59 16.93,7.82 16.93,23.46 v1(17.25,23.77)
  BOTTOM w0.178: v1(35.06,38.84) 35.22,38.68 35.22,36.43 v2(35.24,36.41) 35.22,36.4 35.22,35.87 34.74,35.38 34.74,34 25.22,24.48 17.95,24.48 v1(17.25,23.77)
PCIE_SMDAT0: length 4.7
  TOP w0.178: U10.4 33.24,43.24 32.91,43.56 32.91,44.68 R13.2 33.28,46.13 RE7.2
PCIE_SMDAT1: length 3.8
  TOP w0.178: U10.7 29.67,41.94 29.28,42.33 R15.2 28.39,42.33 28.17,42.11 28.17,41.79 27.91,41.53 RE9.2
PCIE_WAKE_N: length 82.5
  TOP w0.178: v1(32.99,56.2) 32.1,56.2 31.13,55.24 31.13,53.34 CN1.B11 ; v1(31.45,36.73) 31.84,36.33 31.84,16.76 24.37,9.29 22.39,9.29 21.31,8.21 21.31,6.08 21.65,5.74 GF1.B11
  BOTTOM w0.178: v1(31.45,36.73) 31.45,37.02 31.18,37.28 31.18,39.87 31.84,40.53 31.84,40.53 33.08,41.76 v2(33.08,45.28) 33.08,46.18 34.4,47.5 34.4,48.62 33.96,49.05 33.96,51.32 33.33,51.95 32.52,51.95 CN1.B11 ; v1(32.99,56.2) 34.51,57.73 35.36,57.73 35.78,58.15 35.78,68.32 33.05,71.05 33.05,71.74 CN2.B11
PERST_N: length 32.3
  TOP w0.178: v1(37.76,62.68) 37.45,62.99 R19.1 36.81,62.36 36.64,62.18 U9.4
  BOTTOM w0.178: CN1.A11 32.51,54.89 33.55,55.92 35.27,55.92 35.91,56.56 35.91,57.52 37.33,58.95 37.81,58.95 38.3,59.44 38.3,62.14 v1(37.76,62.68) 37.92,62.84 v2(37.92,66.04) 37.92,68.39 36.24,70.07 36.24,71.39 35.17,72.46 35.17,73.12 35.53,73.48 35.53,74.54 34.38,75.69 32.57,75.69 CN2.A11
PERST_N_1: length 6.1
  TOP w0.178: R6.1 38.85,62.36 v2(38.85,63.06) 38.36,63.56 38.02,63.56 37.8,63.79 37.8,65.13 36.57,66.36 U8.4
PERST_N_1_R: length 6.6
  TOP w0.178: v2(39.58,61.21) 39.58,61.23 39.25,60.9 R6.2 38.31,60.86 38.31,59.19 37.71,58.59 36.29,58.59 35.99,58.9 U9.2
PERST_O_1_R: length 5.5
  TOP w0.178: U8.1 35.08,63.87 34.8,63.58 v2(33.66,63.58) 33.66,62.87 33.83,62.7 R17.2 32.96,62.29 32.89,62.36 R3.2
PERST_O_2_R: length 4.3
  TOP w0.178: U9.1 34.96,59.24 R20.2 R4.2
RESET_IN: length 4.5
  TOP w0.178: R1.2 24.32,66.63 C19.1 R2.1 27.06,66.63 27.59,67.16 U1.3
RESET_O_1: length 3.6
  TOP w0.178: U1.2 29.64,63.87 29.84,63.66 30.56,63.66 v2(30.68,63.53) 31.23,62.99 R3.1
RESET_O_2: length 1.8
  TOP w0.178: R4.1 30.79,60.13 30.24,59.59 U2.2
RESET_P3V3_IN: length 5.4
  TOP w0.178: v2(28.53,63.4) 28.62,63.31 U2.3 26.92,61.82 26.38,61.28 C23.1 26.21,62.29 R5.1
RSVD0: length 7.9
  TOP w0.178: GF1.B30 42.65,11.42 TP6.1
RSVD1: length 8.7
  BOTTOM w0.178: GF1.A19 31.65,6.2 32.45,7 TP7.1
S0_PCIE_SMCLK: length 11.5
  TOP w0.178: RE1.1 32.28,47.42 v1(32.81,47.95)
  BOTTOM w0.178: v1(32.81,47.95) 32.39,48.37 26.98,48.37 26.13,49.22 26.13,52.35 CN1.B5
S0_PCIE_SMDAT: length 9.5
  TOP w0.178: v1(33.72,47.92) 33.72,47.45 RE7.1
  BOTTOM w0.178: v1(33.72,47.92) 33.72,48.1 33.03,48.8 27.58,48.8 27.09,49.29 CN1.B6
S0_SMB_ALERT_B12_N: length 3.1
  TOP w0.178: RE4.1 35.29,48.19 35.09,48.39 CN1.B12
S0_SMB_CLK_A32: length 13.3
  TOP w0.178: CN1.A32 55.09,56.96 54.32,57.73 48.61,57.73 46.07,60.27 44.5,60.27 43.94,60.83 RE2.2
S0_SMB_DAT_A33: length 16.9
  TOP w0.178: RE3.2 43.55,61.97 44.83,60.7 46.25,60.7 48.79,58.16 55.16,58.16 56.09,57.23 CN1.A33
S1_PCIE_SMCLK: length 42.4
  TOP w0.178: RE10.1 25.7,40.38 v1(25.67,40.35)
  BOTTOM w0.178: v1(25.67,40.35) 25,41.03 25,41.65 25.11,41.76 25.11,48.43 24.17,49.37 22.57,49.37 22.09,49.85 22.09,50.82 23.05,51.78 23.05,55.14 22.54,55.66 21.81,56.39 21.81,57.93 19.24,60.5 19.24,68.73 22.19,71.67 25.06,71.67 CN2.B5
S1_PCIE_SMDAT: length 40.7
  TOP w0.178: RE9.1 25.83,41.53 v1(25.67,41.37)
  BOTTOM w0.178: v1(25.67,41.37) 25.54,41.5 25.54,48.61 24.17,49.98 24.17,50.72 25.14,51.68 25.14,55.26 24.5,55.9 22.91,55.9 22.24,56.57 22.24,58.11 19.68,60.68 19.68,68.55 20.9,69.77 26.15,69.77 CN2.B6
S1_SMB_ALERT_B12_N: length 6.9
  TOP w0.178: CN2.B12 35.09,69.02 36.98,67.13 36.98,67 37.88,66.1 37.88,66.1 38.53,65.45 RE8.1
S1_SMB_CLK_A32: length 34.7
  TOP w0.178: RE5.2 40.44,63.95 40.44,64.35 37.46,67.32 37.46,67.33 36.95,67.84 36.95,67.84 35.6,69.18 v1(35.6,69.41) ; v1(34.66,71.95) 35.04,72.33 35.04,72.97 36.34,74.26 42.59,74.26 43.12,74.8 43.12,75.69 43.82,76.39 54.27,76.39 CN2.A32
  BOTTOM w0.178: v1(34.66,71.95) 35.12,71.95 35.93,71.14 35.93,69.74 v1(35.6,69.41)
S1_SMB_DAT_A33: length 33.2
  TOP w0.178: CN2.A33 55.26,76.03 45.42,76.03 44.98,75.58 44.98,74.39 44.42,73.83 37.69,73.83 37.1,73.25 37.1,72.05 36.25,71.19 36.25,69.17 41,64.42 41,64.12 RE6.2
SLOT0_CONFIG: length 38.5
  TOP w0.178: v1(70.5,39.34) 71.07,39.9 R33.1
  BOTTOM w0.178: GF1.A50 62.65,6.32 63.84,7.5 63.84,9.43 65.7,12.09 68.05,25.45 68.11,25.75 68.83,29.85 69.72,34.89 v2(69.99,36.55) 70.29,38.16 v1(70.5,39.34)
SLOT0_ID_0: length 6.1
  TOP w0.178: R7.1 44.09,58.89 44.09,56.36 42.61,54.89 CN1.A19
SLOT0_ID_1: length 3.6
  TOP w0.178: R8.2 51.55,48.84 CN1.B30
SLOT1_CONFIG: length 37.5
  TOP w0.178: R35.1 91,39.62 v1(91,38.93)
  BOTTOM w0.178: v1(91,38.93) 91.25,37.53 v2(91.45,36.47) 91.73,34.77 92.4,30.97 94,21.92 94.08,21.46 95.65,12.56 GF1.A83
SLOT1_ID_0: length 26.7
  TOP w0.178: R9.2 18.26,75.22 19.35,76.31 40.99,76.31 CN2.A19
SLOT1_ID_1: length 4.2
  TOP w0.178: R10.2 54.29,67.84 53.09,69.04 CN2.B30

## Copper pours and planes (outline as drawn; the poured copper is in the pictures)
GND on TOP: 122.45,24.47 122.26,24.66 115.93,39.36 115.93,39.49 109.15,59.6 109.04,59.82 109.04,77.74 138.3,77.74 138.47,77.67 138.54,77.5 138.54,36.51 128.29,36.51 127.88,36.1 127.88,28.46 123.89,24.47
GND on TOP: 26.01,42.14 25.91,42.25 25.91,45.11 25.38,45.64 25.38,47.39 25.93,47.94 28.96,47.94 29.03,47.86 29.03,47.33 28.99,47.28 28.58,47.28 28.18,46.88 28.18,42.83 27.48,42.14 ; 5 cut-outs
GND on TOP: 0.76,35.07 0.76,77.5 0.83,77.67 1,77.74 15.47,77.74 15.74,77.46 15.74,73.66 15.62,73.54 10.97,73.54 10.62,73.19 10.62,71.28 11.55,70.35 11.55,58.86 8.44,55.75 8.44,35.51 7.99,35.07 ; 25 cut-outs
GND on TOP: 25.09,63.13 24.95,63.27 24.95,65.41 24.98,65.44 24.98,65.76 25.15,65.93 28.06,65.93 28.44,65.55 28.44,63.24 28.33,63.13 ; 4 cut-outs
GND on BOTTOM: 10.92,45.27 10.92,63.97 7.24,67.65 0.76,67.65 0.76,77.5 0.83,77.67 1,77.74 22.13,77.74 22.13,76.87 17.59,72.33 17.59,57.95 19.33,56.21 19.33,52.98 11.46,45.11 11.08,45.11
GND on BOTTOM: 136.57,24.72 136.51,24.73 136.45,24.75 135.68,25.2 135.59,25.28 135.56,25.4 135.56,26.96 134.57,28.83 132.47,29.07 127.27,29.07 127.27,29.06 124.49,29.06 116.79,36.76 116.79,38.17 110.86,44.1 110.86,54.85 109.04,56.67 109.04,77.74 138.3,77.74 138.47,77.67 138.54,77.5 138.54,24.96 138.47,24.79 138.3,24.72
GND on L2GND, L3GND: 11.76,2.54 11.76,22.96 11.25,24.21 10,24.72 8.94,24.72 8.82,24.75 8.74,24.84 8.29,25.61 8.27,25.67 8.26,25.73 8.26,26.96 6,29.22 3.74,26.96 3.74,25.73 3.73,25.67 3.71,25.61 3.26,24.84 3.18,24.75 3.06,24.72 1,24.72 0.83,24.79 0.76,24.96 0.76,77.5 0.83,77.67 1,77.74 138.3,77.74 138.47,77.67 138.54,77.5 138.54,24.96 138.47,24.79 138.3,24.72 136.57,24.72 136.51,24.73 136.45,24.75 135.68,25.2 135.59,25.28 135.56,25.4 135.56,26.96 133.3,29.22 131.04,26.96 131.04,25.4 131.01,25.28 130.92,25.2 130.15,24.75 130.09,24.73 130.03,24.72 129.3,24.72 128.05,24.21 127.54,22.96 127.54,2.54 24.86,2.54 24.86,7.45 23.15,9.16 21.44,7.45 21.44,2.54
P3V3 on TOP: 26.31,67.91 25.7,68.52 25.7,72.61 26.18,73.09 26.18,75.23 26.93,75.98 32.38,75.98 32.61,75.75 32.61,73.91 31.6,72.91 31.6,72.32 30.37,71.09 30.37,68.68 29.61,67.91
P3V3 on TOP: 18.13,7 17.34,7.79 17.34,9.7 17.84,10.21 17.84,21.72 18.05,21.92 18.05,21.93 18.39,22.27 18.39,23.14 17.87,23.67 17.87,26.14 17.05,26.96 16.56,26.96 16,27.52 16,35.9 16.02,35.92 16.02,38.4 16.94,39.32 20.29,39.32 20.37,39.39 20.37,48 21.4,49.04 22.68,49.04 25.41,51.77 25.41,51.79 25.56,51.94 25.56,55.8 25.55,55.81 25.55,56.11 21.48,60.18 21.48,64.82 21.87,65.2 23.8,65.2 24.02,65.42 24.02,65.76 24.1,65.84 24.64,65.84 24.64,63.1 24.92,62.83 25.31,62.83 25.54,62.59 25.54,59.99 27.09,58.44 31.48,58.44 32,57.92 32,56.64 30.52,55.16 30.52,53.01 30.13,52.63 30.13,49.43 28.95,48.25 25.78,48.25 25.09,47.56 25.09,45.46 25.54,45 25.54,44.99 25.6,44.93 25.6,42.25 25.04,41.69 25.04,40.9 24.43,40.28 24.43,34.04 20.58,30.19 20.58,12.56 20.59,12.56 20.59,11.27 19.76,10.45 19.76,9.62 19.49,9.34 19.35,9.34 19.35,7.17 19.18,7 ; 11 cut-outs
P3V3 on BOTTOM: 21.22,6.92 20.84,6.53 18.6,6.53 18.31,6.82 18.31,12.3 18.52,12.5 20.85,12.5 21.22,12.14
P3V3 on BOTTOM: 21.21,62.97 21.21,68.27 22.15,69.21 27.76,69.21 28.02,69.47 28.02,75.81 28.03,75.82 28.03,77.49 28.18,77.64 31.64,77.64 31.91,77.37 31.91,76.35 31.26,75.71 31.26,72.14 30.2,71.08 30.2,67.45 29.51,66.76 26.12,66.76 25.4,66.04 25.4,63 24.94,62.54 21.65,62.54
P3V3_AUX on TOP: 32.58,63.36 32.1,63.84 32.1,65.36 32.63,65.89 32.63,66.93 33.22,67.52 33.22,68.28 32.93,68.57 32.3,68.57 30.52,70.35 30.52,71 30.96,71.45 33.41,71.45 34.41,70.44 34.41,68.95 35.28,68.09 35.28,67.08 35.39,66.97 35.39,65.77 35.35,65.73 34.5,65.73 34.25,65.48 34.25,63.95 33.66,63.36 ; 4 cut-outs
P3V3_AUX on TOP: 20.2,6.06 20.01,6.25 20.01,9.32 22.07,11.37 23.54,11.37 29,16.83 29,38.65 28.48,39.17 28.48,40.51 28.56,40.59 29.2,40.59 29.35,40.44 29.35,40.1 30.57,38.88 30.57,16.38 24.27,10.08 22.57,10.08 21,8.5 21,6.06 ; 1 cut-out
P3V3_AUX on TOP: 32.83,59.66 32.66,59.84 31.99,59.84 31.89,59.93 31.89,60.59 32.04,60.74 32.04,61.54 32.19,61.69 34.87,61.69 35.16,61.98 35.54,61.98 35.61,61.91 35.61,60.69 35.5,60.58 34.97,60.58 34.97,60.58 34.84,60.58 34.79,60.53 34.79,59.81 34.65,59.66 ; 4 cut-outs
P3V3_AUX on TOP: 28.55,42.93 28.5,42.98 28.5,46.74 28.73,46.97 29.11,46.97 29.33,47.19 29.33,48 30.43,49.1 30.43,51.19 30.66,51.42 31.9,51.42 32.79,50.53 32.79,49.08 31.67,47.96 31.67,44.66 31.25,44.23 30.82,44.23 30.49,43.9 29.33,43.9 28.97,43.54 28.97,42.93 ; 4 cut-outs
P3V3_AUX on BOTTOM: 31.64,47.59 31.26,47.97 28.97,47.97 27.77,46.77 27.77,38.61 28.59,37.78 30.23,37.78 31.64,39.19
P3V3_AUX on BOTTOM: 29.76,66.1 28.35,66.1 27.24,64.99 27.24,50.54 28.48,49.3 33.15,49.3 33.55,49.7 33.55,51.65 32.44,52.76 32.44,56.6 34.72,58.89 34.72,63.44 35.31,64.03 35.31,68.13 32.05,71.39 30.84,71.39 30.48,71.04 30.48,66.82
P12V on TOP: 12.21,6.6 11.92,6.88 11.92,29.67 11.08,30.51 11.08,34.75 11.06,34.77 11.06,35.33 8.64,37.75 8.64,55.29 12,58.66 12,70.33 10.93,71.41 10.93,72.86 11.13,73.06 16.88,73.06 18.76,74.94 18.76,74.96 19.75,75.95 25.1,75.95 25.25,75.8 25.25,70.79 24.59,70.13 24.59,67.28 24.52,67.21 23.87,67.21 23.62,66.96 21.62,66.96 21.09,66.43 21.09,59.95 23.05,57.99 23.05,57.76 25.21,55.61 25.21,51.99 22.51,49.29 16.08,49.29 14.59,47.8 14.59,40.09 15.49,39.19 15.49,7.47 15.36,7.34 14.63,7.34 13.88,6.6 ; 18 cut-outs
P12V on BOTTOM: 12.42,6.36 12.22,6.56 12.22,11.44 12.6,11.82 15.19,11.82 15.47,11.53 15.47,7.6 14.23,6.36

Small or netless copper shapes (teardrops, artwork), in the pictures only: 2 on TOP, 2 on BOTTOM

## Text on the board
Ref Des/Silkscreen Top: LBC 2slot PCIE riser | MADE IN TAIWAN | B48.01705.00SA | 16370-SA
User.27: Anti pad to Anti pad Check,Aug 04 22:58:35 2016,9 errors | BGA From Routing Tab Check,Jul 22 11:04:21 2016,Warning | Board/Panel Size Check,Aug 04 23:24:31 2016,Passed | Broken Plane Check,Aug 04 23:04:24 2016,Passed | Bus Via Check,Aug 04 23:07:15 2016,Passed | Capacitor Orrientation Check,Aug 04 22:55:28 2016,Warning | Cline Between Pin or Via check,Aug 04 23:07:24 2016,25 errors | Comp From Routing Tab Check,Aug 04 22:57:15 2016,1 errors | Comp Mark to Comp Check,Aug 04 23:07:05 2016,Passed | Comp Pad To Comp Pad Check,Aug 04 22:55:57 2016,Passed | Component On Edge Check,Aug 04 22:56:03 2016,10 errors | Component Overlap Check,Aug 04 22:55:34 2016,2 errors | Component[Pitch] On Edge Check,Aug 04 22:57:10 2016,Passed | Cross Moat Check,Aug 04 22:58:53 2016,13 errors | Cross Thermal And Anti Pad Check,Aug 04 23:24:04 2016,Passed | DFT Requirements,Aug 04 23:06:50 2016,1 errors | DIMM 10mm Area Check,Aug 04 22:57:28 2016,Warning | Diffpair Gap Check,Aug 04 23:18:34 2016,266 errors | Drill Table Check,Aug 04 23:24:17 2016,Passed | GF Inner Layer Shape Check,Aug 04 23:00:10 2016,Passed | Height Limit Check,Aug 04 22:57:32 2016,8 errors | Highspeed GND Check,Jul 22 11:07:39 2016,Warning | Hole Clearance Check,Aug 04 22:59:46 2016,4 errors | Impedance Stackup Check,Aug 04 23:18:26 2016,Warning | Inner Layer for Holes Check,Aug 04 23:24:31 2016,Passed | Inner Trace Clearance Check,Aug 04 23:00:01 2016,Passed | LF HASL Via Check,Aug 04 23:01:33 2016,175 errors | Library Path Check,Aug 04 22:57:42 2016,16 errors | Markin Check,Aug 04 22:57:54 2016,Warning | Markout And Tooling Hole Check,Aug 04 22:57:58 2016,Passed | Moat Attribute Check,Aug 04 03:12:34 2016,26 errors | NPTH Clearance Check,Aug 04 22:59:56 2016,Passed | Outline Clearance Check,Aug 04 23:00:15 2016,Passed | Phase Power Clearance Check,Aug 04 23:18:18 2016,Warning | Placement Balance Check,Aug 04 22:58:05 2016,72 errors | Power Exit On Two Pins Check,Aug 04 23:00:38 2016,9 errors | Proper Pad Entry Check,Aug 04 23:00:21 2016,15 errors | Purge Padstack Check,Aug 04 03:12:34 2016,Passed | Refdes Orientation Check,Aug 04 23:24:31 2016,Passed | Reference Plane Check,Aug 04 23:20:44 2016,Warning | Shape Apperture Check,Aug 04 22:59:22 2016,332 errors | Silkscreen From BO Check,Jul 22 11:06:27 2016,Passed | Silkscreen Overlap Check,Aug 04 23:07:01 2016,Passed | Small Comp Near Big Comp Check,Aug 04 23:24:31 2016,Passed | Solder Bump Check,Jul 22 11:06:02 2016,272 errors | Split Plane Check,Aug 04 22:59:40 2016,Passed | TP Percentage Check,Aug 04 23:05:57 2016,Passed | TP To Golden Finger Check,Aug 04 23:06:01 2016,Passed | TP Violations Check,Aug 04 23:05:00 2016,1 errors | Thermal Reduction Check,Aug 04 23:04:30 2016,Passed | Thru Pin To SMD Clearance Check,Aug 04 22:58:19 2016,Passed | Thru Pin To Thru Via Check,Aug 04 23:04:34 2016,Passed | Trace To Trace Spacing Check,Aug 04 23:01:22 2016,Passed | Trace Width Check,Aug 04 23:20:25 2016,112 errors | Traces between differential vias/pins,Jul 22 11:07:40 2016,6 errors | Via Aspect Ratio Check,Jul 22 11:05:51 2016,Passed | Via Check,Jul 22 11:05:51 2016,Passed | Via Connectivity,Aug 04 23:04:00 2016,3 errors | Via On Moat Check,Aug 04 23:02:36 2016,Passed | Via On Pad Check,Aug 04 23:02:31 2016,Passed | Via To Via Per Net Check,Aug 04 23:03:47 2016,Warning | Via To Via Spacing Check,Aug 04 23:02:42 2016,39 errors | Via Type Check,Jul 22 11:05:51 2016,18 errors | sklCheckAssemblyIntersection,Jul 22 11:08:08 2016,Passed | sklCheckCoPlanar,Jul 22 11:08:08 2016,Passed | sklCheckCrossMoat_bkit,Jul 22 11:08:08 2016,Passed | sklCheckHdiVia,Jul 22 11:08:08 2016,Passed | sklCheckKeepoutOnViaAndComp,Jul 22 11:08:08 2016,Passed | sklCheckMinSpacing,Aug 04 23:24:31 2016,Passed | sklCheckReferencePlane_art,Jul 22 11:08:08 2016,Passed | sklCheckReferencePlane_old,Jul 22 11:08:08 2016,Passed | sklPcbDetailCheck,Jul 22 11:08:09 2016,4 errors
User.45: ByImpedance:50.0@_REF_L1=("7.0(L1)")|Type="SE"|_REF_L4=("7.0(L4)")|imp="50.0" | ByImpedance:85.0@_REF_L1=("7.0/5.0(L1)")|Type="DP"|_REF_L4=("7.0/5.0(L4)")|imp="85.0" | LayerIndex:nil | Source:Wiwynn_16370-SA_Leopard_BW_Channel_1x16_1x8_PCIe_Riser_4L_Stackup_RPT_20160718.xlsx | artWorks:("_REF_L4" "_REF_L1") | gtImpOutlineUsed:BOARD GEOMETRY/PANEL_OUTLINE | 1 | 2 | 3 | 4 | 5 | 6 | Note:Refer to DRILL layer for ELLIPSE drill direction | FIGURE | SIZE | 12.0 | 16.0 | 20.0 | 28.0 | 224.0 | ELLIPSE | 86.0 | 93.0 | DRILL CHART: TOP to BOTTOM | ALL UNITS ARE IN MILS | PLATED | NON-PLATED | QTY | 210 | 29 | 12 | 262 | 16370-SA | B48.01705.00SA | LBC 2slot PCIE riser | MADE IN TAIWAN | This gerber is just for your reference to find the DP impedance traces in layer L1. | This gerber is just for your reference to find the DP impedance traces in layer L4. | This gerber is just for your reference to find the SE impedance traces in layer L1. | This gerber is just for your reference to find the SE impedance traces in layer L4. | DP IMPEDANCE TABLE: L1 | DP IMPEDANCE TABLE: L4 | SE IMPEDANCE TABLE: L1 | SE IMPEDANCE TABLE: L4 | * - Denotes that WIDTH | is NOT used in this layer | inside board outline. | Model | PCB_NO | 16370 | VER. | SA | Layer | DRILL | GOLD_T | L1 | L2GND | TMASK | TPLACE | TSILK | TSMD | IMP(Ohm) | 50.0 | 85.0 | Designer | P09C012 | WIDTH(mils) | 7.0 | 7.0/5.0 | Date | 07/28/2016 | TYPE | SE | DP | BMASK | BPLACE | BSILK | BSMD | GOLD_B | L3GND | L4
